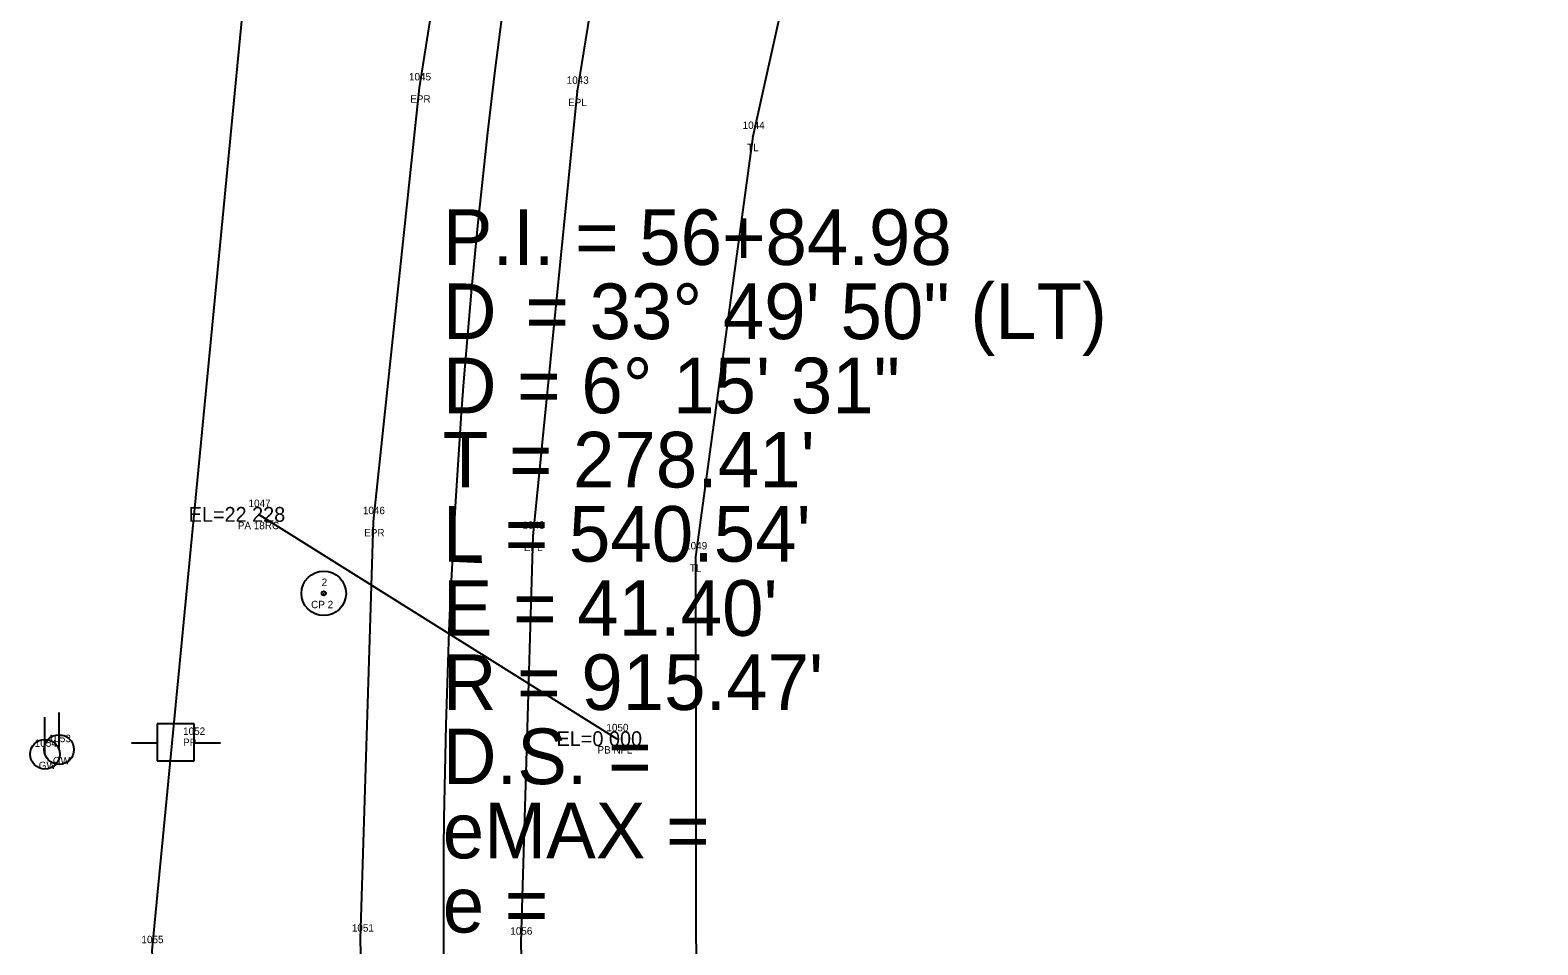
# Model space of a CAD drawing. Extents: x 2432632 to 2433497, y 684847 to 688233.
# Drawn here: x 2432869.4 to 2433072.6, y 687158.3 to 687281.7 of the extents above; entities that cross this region are included whole.
import ezdxf

# ---------------------------------------------------------------- set-up
doc = ezdxf.new("R2010")
doc.units = 0
for name, color, linetype in [('RD_EX_DR_Pipe', 7, 'Continuous'), ('RD_EX_DR_Pipe_txCode', 7, 'Continuous'), ('RD_EX_Road', 7, 'Continuous'), ('RD_EX_Road_txCode', 7, 'Continuous'), ('RD_EX_UT', 7, 'Continuous'), ('RD_EX_UT_txCode', 7, 'Continuous'), ('RD_EX_VEG', 7, 'Continuous'), ('RD_EX_VEG_txCode', 7, 'Continuous'), ('RD_HC_Cl', 7, 'Continuous'), ('RD_HC_Data', 7, 'Continuous'), ('RD_HC_Data_Tic', 7, 'Continuous'), ('RD_HC_txCode', 7, 'Continuous'), ('RD_SMD_Locator', 7, 'Continuous'), ('RD_TX_Pipe_ElevEX', 7, 'Continuous')]:
    doc.layers.add(name, color=color, linetype=linetype)

msp = doc.modelspace()

# ---------------------------------------------------------------- linework, layer by layer
at = {"layer": 'RD_EX_DR_Pipe'}
msp.add_line((2432900.22, 687216.37), (2432948.47, 687186.13), dxfattribs=at)
at = {"layer": 'RD_EX_Road'}
for points in [[(2433130.63, 688090.22), (2433103.18, 687988.73), (2433075.68, 687887.89), (2433049.83, 687790.75), (2433022.33, 687689.17), (2432994.76, 687586.82), (2432966.23, 687480.17), (2432943.15, 687390.42), (2432931.4, 687334.3), (2432921.83, 687273.88), (2432915.64, 687215.4), (2432913.86, 687159.12), (2432915.08, 687107.55), (2432919.97, 687053.4), (2432928.7, 686998.89), (2432946.77, 686924.59), (2432964.57, 686864), (2432997.3, 686766.34), (2433031.44, 686666.38), (2433066.06, 686565.78), (2433098.73, 686469.74)], [(2432986.34, 687474.01), (2432964, 687384.38), (2432952.4, 687330.76), (2432943.09, 687273.42), (2432937.12, 687213.43), (2432935.51, 687158.7), (2432936.54, 687110.38), (2432944.97, 687033.04), (2432950.24, 687002.26), (2432966.49, 686930.23), (2432984.9, 686870.1)]]:
    msp.add_lwpolyline(points, dxfattribs=at)
at = {"layer": 'RD_EX_UT'}
for p, q in [((2432871.4, 687184.03), (2432871.4, 687189.03)), ((2432873.3, 687184.66), (2432873.3, 687189.66)), ((2432891.5, 687188.15), (2432886.5, 687188.15)), ((2432886.5, 687188.15), (2432886.5, 687183.15)), ((2432891.5, 687183.15), (2432891.5, 687188.15)), ((2432883.07, 687185.59), (2432886.54, 687185.59)), ((2432891.43, 687185.59), (2432895.07, 687185.59)), ((2432886.5, 687183.15), (2432891.5, 687183.15))]:
    msp.add_line(p, q, dxfattribs=at)
for centre in [(2432873.3, 687184.66), (2432871.4, 687184.03)]:
    msp.add_circle(centre, 2, dxfattribs=at)
at = {"layer": 'RD_EX_VEG'}
for points in [[(2433112.43, 688094.61), (2433041.17, 687898.89), (2432988.9, 687699.78), (2432947.96, 687578.08), (2432935.9, 687556.87), (2432944.3, 687538.7), (2432913.88, 687397.98), (2432902.4, 687330.02), (2432885.78, 687157.56), (2432894.43, 687032.93), (2432918.07, 686924.4), (2432974.73, 686759.54), (2433073.82, 686456.42), (2433099.9, 686365.23), (2433115.47, 686257.21), (2433114.64, 686158.77), (2433095.68, 686092.78)], [(2433166.25, 688082.87), (2433111.93, 687876.69), (2433067.75, 687703.46), (2433065.05, 687678.03), (2433052.74, 687645.62), (2433005.45, 687469.88), (2432979.96, 687326.61), (2432966.8, 687267.34), (2432959.05, 687210.65), (2432959.25, 687071.62), (2432974.82, 687014.37), (2432998.13, 686938.9), (2433012.99, 686878.7), (2433054.45, 686782.35), (2433123.54, 686586.06), (2433129.82, 686546.35), (2433158.34, 686434.26), (2433192.79, 686274.67), (2433189.42, 686162.6), (2433197.4, 686074.41)]]:
    msp.add_lwpolyline(points, dxfattribs=at)
at = {"layer": 'RD_HC_Cl'}
msp.add_arc((2433840.56, 687163.67), 915.47, 164.98581, 198.81644, dxfattribs=at)
at = {"layer": 'RD_HC_Data'}
for radius in [3, 0.282]:
    msp.add_circle((2432908.97, 687205.72), radius, dxfattribs=at)
at = {"layer": 'RD_HC_Data_Tic'}
msp.add_line((2432926.27, 687210.11), (2432930.26, 687209.91), dxfattribs=at)
at = {"layer": 'RD_SMD_Locator'}
for centre in [(2432921.83, 687273.88), (2432943.09, 687273.42), (2432966.8, 687267.34), (2432900.22, 687216.37), (2432915.64, 687215.4), (2432937.12, 687213.43), (2432959.05, 687210.65), (2432908.97, 687205.72), (2432948.47, 687186.13), (2432913.86, 687159.12), (2432935.51, 687158.7)]:
    msp.add_circle(centre, 0.001, dxfattribs=at)

# ---------------------------------------------------------------- texts
at = {"layer": 'RD_EX_DR_Pipe_txCode'}
for s, p in [('1047', (2432898.83, 687217.37)), ('PA 18RC', (2432897.38, 687214.37)), ('1050', (2432947.05, 687187.13)), ('PB NFL', (2432945.85, 687184.13))]:
    msp.add_text(s, height=1, dxfattribs=at).set_placement(p)
at = {"layer": 'RD_EX_Road_txCode'}
for s, p in [('1045', (2432920.45, 687274.88)), ('1043', (2432941.7, 687274.42)), ('EPR', (2432920.61, 687271.88)), ('EPL', (2432941.89, 687271.42)), ('1046', (2432914.23, 687216.4)), ('1048', (2432935.74, 687214.43)), ('EPR', (2432914.41, 687213.4)), ('EPL', (2432935.92, 687211.43)), ('1051', (2432912.75, 687160.12)), ('1056', (2432934.1, 687159.7))]:
    msp.add_text(s, height=1, dxfattribs=at).set_placement(p)
at = {"layer": 'RD_EX_UT_txCode'}
for s, p in [('1053', (2432871.91, 687185.66)), ('1052', (2432890.01, 687186.64)), ('1054', (2432870.02, 687185.03)), ('PP', (2432890.01, 687185.14)), ('GW', (2432870.56, 687182.03)), ('GW', (2432872.46, 687182.66))]:
    msp.add_text(s, height=1, dxfattribs=at).set_placement(p)
at = {"layer": 'RD_EX_VEG_txCode'}
for s, p in [('1044', (2432965.41, 687268.34)), ('TL', (2432966.02, 687265.34)), ('1049', (2432957.66, 687211.65)), ('TL', (2432958.28, 687208.65)), ('1055', (2432884.4, 687158.56))]:
    msp.add_text(s, height=1, dxfattribs=at).set_placement(p)
at = {"layer": 'RD_HC_Data'}
for s, p in [('P.I. = 56+84.98', (2432925, 687250)), ('D', (2432925, 687240)), ('    = 33%%d 49\' 50" (LT)', (2432925, 687240)), ('D = 6%%d 15\' 31"', (2432925, 687230)), ("T = 278.41'", (2432925, 687220)), ("L = 540.54'", (2432925, 687210)), ("E = 41.40'", (2432925, 687200)), ("R = 915.47'", (2432925, 687190)), ('D.S. = ', (2432925, 687180)), ('eMAX = ', (2432925, 687170)), ('e = ', (2432925, 687160))]:
    msp.add_text(s, height=7.5, dxfattribs=at).set_placement(p)
at = {"layer": 'RD_HC_txCode'}
for s, p in [('2', (2432908.68, 687206.72)), ('CP 2', (2432907.26, 687203.72))]:
    msp.add_text(s, height=1, dxfattribs=at).set_placement(p)
at = {"layer": 'RD_TX_Pipe_ElevEX'}
for s, p in [('EL=22 228  ', (2432890.76, 687215.37)), ('EL=0 000 ', (2432940.33, 687185.13))]:
    msp.add_text(s, height=2, dxfattribs=at).set_placement(p)

doc.saveas('drawing.dxf')
